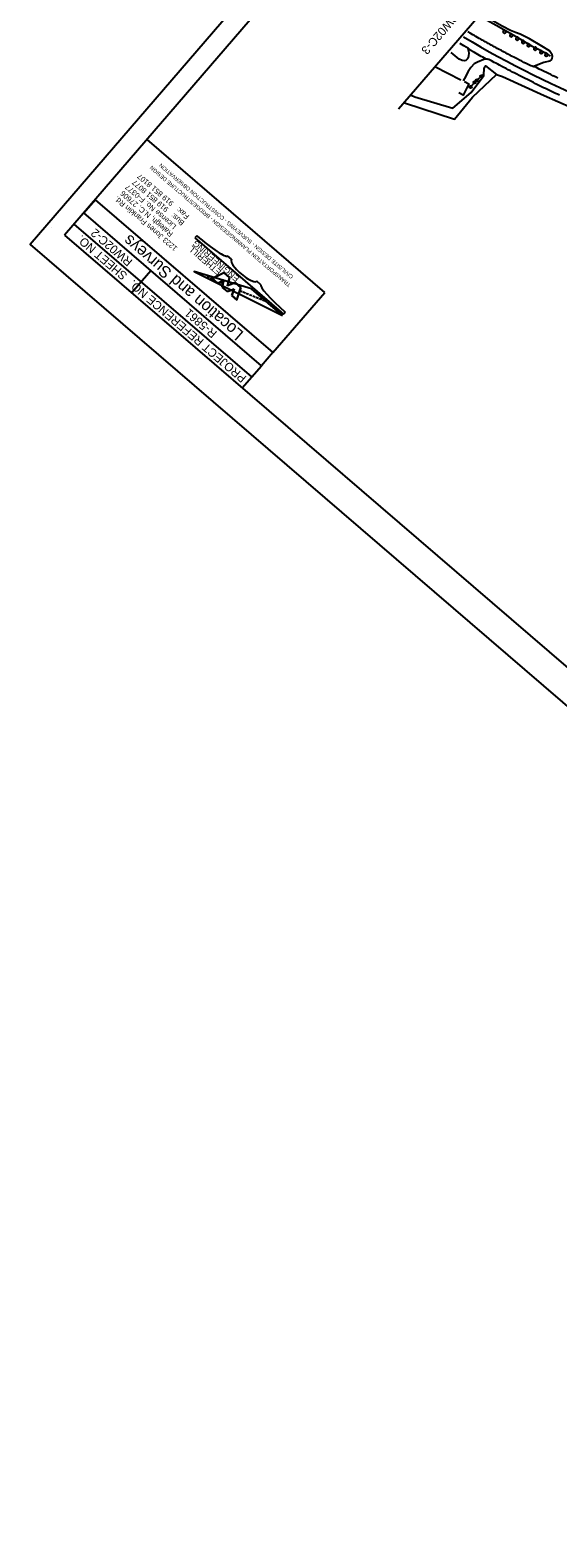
# Model space of a CAD drawing. Extents: x 478596 to 483012, y 490885 to 495165.
# Drawn here: x 478596 to 479587, y 490885 to 493722 of the extents above; entities that cross this region are included whole.
import ezdxf

# ---------------------------------------------------------------- set-up
doc = ezdxf.new("R2010")
doc.units = 0
for name, color, linetype in [('CTL Sheet Border CELL', 7, 'Continuous'), ('CTL Sheet Notes CELL', 7, 'Continuous'), ('Exist Horizontal Alignment', 7, 'Continuous'), ('Exist Other Culture Area Outline', 7, 'Continuous'), ('Exist Other Culture Fence Line', 7, 'Continuous'), ('Exist Other Culture Sign', 7, 'Continuous'), ('Exist Other Culture Sign Post CELL', 7, 'Continuous'), ('Exist Roads EOP', 7, 'Continuous'), ('Exist Roads Soil', 7, 'Continuous'), ('Exist Vegetation Hedge Row', 7, 'Continuous'), ('Exist Vegetation Shrub CELL', 7, 'Continuous'), ('Exist Vegetation Woods Line', 7, 'Continuous'), ('Matchline', 7, 'Continuous'), ('Matchline Text', 7, 'Continuous'), ('Sheet Plot Border Outside CELL', 7, 'Continuous')]:
    doc.layers.add(name, color=color, linetype=linetype)

msp = doc.modelspace()

# ---------------------------------------------------------------- linework, layer by layer
at = {"layer": 'CTL Sheet Border CELL'}
for p, q in [((479149.5, 493228.2), (478815.6, 493515.6)), ((478636, 493349.5), (478636, 493349.5)), ((478636, 493349.5), (478636, 493349.5)), ((479012.7, 493069.4), (478678.8, 493356.8)), ((478596, 493318.3), (478596, 493318.3)), ((478786.6, 493227.4), (478822.7, 493269.4)), ((479052, 493115), (479149.4, 493228.2)), ((478994.6, 493048.4), (479030.7, 493090.3))]:
    msp.add_line(p, q, dxfattribs=at)
for points in [[(478660.7, 493335.7), (481178.4, 491168.5), (482695.4, 492930.9), (480177.7, 495098.1)], [(479030.7, 493090.3), (478696.8, 493377.7), (478718.1, 493402.4), (479052, 493115)]]:
    msp.add_lwpolyline(points, close=True, dxfattribs=at)
at = {"layer": 'CTL Sheet Notes CELL'}
for p, q in [((478909, 493334.9), (478905.7, 493331.1)), ((478905.7, 493331.1), (479072.2, 493187.3)), ((478974.3, 493290.6), (478966.7, 493297.2)), ((478932.7, 493255.3), (478928.1, 493257.3)), ((478938.8, 493252.7), (478934.2, 493254.7)), ((478937.8, 493254.1), (478947.9, 493245.4)), ((478960.4, 493264.7), (478938.4, 493254)), ((478938.4, 493254), (478947.9, 493245.8)), ((478947.9, 493245.8), (478959.8, 493251.6)), ((478947.9, 493245.4), (478959.3, 493251)), ((478959.3, 493251), (478956.4, 493238.1)), ((478959.8, 493251.6), (478956.7, 493238.2)), ((478970.5, 493256), (478960.4, 493264.7)), ((478970.9, 493256.1), (478960.5, 493265.1)), ((478966.9, 493240.4), (478970.5, 493256)), ((478967.4, 493240.9), (478970.9, 493256.1)), ((479029.7, 493242.7), (479022.2, 493249.2)), ((478957.3, 493245), (478952.7, 493246.9)), ((478956.4, 493238.1), (478966.1, 493229.6)), ((478956.7, 493238.2), (478966.2, 493230)), ((478966.1, 493229.6), (478978.5, 493234.5)), ((478966.2, 493230), (478979.1, 493235)), ((478981.8, 493246.2), (478966.9, 493240.4)), ((478981.9, 493246.6), (478967.4, 493240.9)), ((478978.5, 493234.5), (478974.6, 493222.3)), ((478974.6, 493222.3), (478984.6, 493213.6)), ((478979.1, 493235), (478975, 493222.4)), ((478975, 493222.4), (478984.5, 493214.2)), ((478991.9, 493237.5), (478981.8, 493246.2)), ((478992.3, 493237.6), (478981.9, 493246.6)), ((478984.5, 493214.2), (478991.9, 493237.5)), ((478984.6, 493213.6), (478992.3, 493237.6)), ((478994.2, 493229.5), (478989.5, 493231.4)), ((479000.3, 493226.9), (478995.7, 493228.9)), ((479006.4, 493224.3), (479001.8, 493226.3)), ((479012.6, 493221.8), (479008, 493223.7)), ((479018.7, 493219.2), (479014.1, 493221.1)), ((479024.9, 493216.6), (479020.3, 493218.5)), ((479031, 493214), (479026.4, 493215.9)), ((479037.2, 493211.4), (479032.6, 493213.4)), ((479072.2, 493187.3), (479075.5, 493191.1))]:
    msp.add_line(p, q, dxfattribs=at)
msp.add_lwpolyline([(479070, 493184.8), (479012, 493234.9), (478904.3, 493267.3)], close=True, dxfattribs=at)
msp.add_lwpolyline([(478960.5, 493265.1), (478960.1, 493265), (478937.8, 493254.1)], dxfattribs=at)
for centre, major_axis, ratio, start_param, end_param in [((478915, 493341.8), (-51.7, 44.7), 0.134146, 1.570796, 3.141593), ((478998.2, 493269.9), (-24, 20.7), 0.289474, 0, 3.141593), ((479081.4, 493198), (51.7, -44.7), 0.134146, 3.141593, 4.712389)]:
    msp.add_ellipse(centre, major_axis=major_axis, ratio=ratio, start_param=start_param, end_param=end_param, dxfattribs=at)
at = {"layer": 'Exist Horizontal Alignment'}
msp.add_arc((480448.9, 495467.9), 2043, 239.4405, 247.8014, dxfattribs=at)
at = {"layer": 'Exist Other Culture Area Outline'}
for points in [[(479356.1, 493653), (479405.4, 493628.2)], [(479412.4, 493624.7), (479420.3, 493620.8), (479409.7, 493599.3), (479401.4, 493603.3)]]:
    msp.add_lwpolyline(points, dxfattribs=at)
at = {"layer": 'Exist Other Culture Fence Line'}
for points in [[(479517.7, 493704.2), (479494.8, 493716.8), (479471.4, 493730), (479449, 493742.6), (479438.1, 493748.4)], [(479517.7, 493704.2), (479538.3, 493692.1), (479551.1, 493685.6), (479562.8, 493679.5), (479573.1, 493672.4)]]:
    msp.add_lwpolyline(points, dxfattribs=at)
at = {"layer": 'Exist Other Culture Sign'}
for p, q in [((479433.4, 493625.7), (479422, 493613.4)), ((479446.4, 493637.7), (479434.5, 493626.2))]:
    msp.add_line(p, q, dxfattribs=at)
at = {"layer": 'Exist Other Culture Sign Post CELL'}
for centre, radius in [((479423.7, 493614.8), 2.18), ((479431.2, 493623.1), 2.18), ((479431.2, 493623.1), 0.24), ((479435.9, 493627), 2.18), ((479435.9, 493627), 0.24), ((479444, 493634.9), 2.18), ((479444, 493634.9), 0.24), ((479423.7, 493614.8), 0.24)]:
    msp.add_circle(centre, radius, dxfattribs=at)
at = {"layer": 'Exist Roads EOP'}
for points in [[(479587.7, 493631.1), (479583.1, 493633.4), (479578.4, 493635.7), (479574.3, 493637.8), (479570.3, 493639.7), (479566.2, 493641.7), (479561.9, 493643.8), (479557.1, 493646.1), (479552.6, 493648.4), (479547.3, 493651), (479544.6, 493652.3), (479543.3, 493652.8), (479540.5, 493653.2), (479539.4, 493653.6), (479536.8, 493654.7), (479533.2, 493656.3), (479527.8, 493658.9), (479523.9, 493660.8), (479519.8, 493662.9), (479515.6, 493665), (479511, 493667.4), (479506, 493669.9), (479500.7, 493672.7), (479497.9, 493674.2), (479495.1, 493675.7), (479492.3, 493677.2), (479489.6, 493678.7), (479486.8, 493680.1), (479484.1, 493681.6), (479481.4, 493683), (479476.2, 493685.8), (479473.6, 493687.2), (479470.9, 493688.7), (479468.1, 493690.2), (479465.3, 493691.7), (479462.5, 493693.3), (479459.7, 493694.9), (479456.8, 493696.4), (479454, 493698), (479451.2, 493699.6), (479448.3, 493701.2), (479445.5, 493702.8), (479442.6, 493704.5), (479439.6, 493706.1), (479436.7, 493707.8), (479433.7, 493709.5), (479430.7, 493711.3), (479427.8, 493713), (479422.7, 493716), (479418.7, 493718.4)], [(479590.8, 493599), (479586.9, 493600.8), (479583.1, 493602.6), (479579.3, 493604.4), (479575.5, 493606.1), (479571.7, 493607.9), (479568.1, 493609.7), (479564.4, 493611.5), (479560.8, 493613.3), (479557.1, 493615.1), (479553.3, 493617), (479549.4, 493618.9), (479545.5, 493620.8), (479541.6, 493622.8), (479537.8, 493624.7), (479534, 493626.6), (479530.3, 493628.5), (479526.4, 493630.5), (479522.6, 493632.4), (479518.7, 493634.4), (479514.7, 493636.4), (479510.7, 493638.5), (479506.7, 493640.5), (479502.6, 493642.6), (479498.5, 493644.7), (479494.4, 493646.9), (479490.3, 493649.1), (479486.1, 493651.2), (479482.1, 493653.4), (479478.2, 493655.4), (479474.6, 493657.3), (479471.2, 493659.1), (479468.2, 493660.7), (479463, 493663.5), (479457.6, 493666), (479455.9, 493666.6), (479455.2, 493666.8), (479453.5, 493667), (479452.9, 493667.2), (479449.5, 493669), (479446.7, 493670.5), (479443.5, 493672.2), (479440.3, 493674), (479437.1, 493675.8), (479433.9, 493677.6), (479431, 493679.2), (479428.6, 493680.6), (479423.9, 493683.5), (479422.9, 493684.3), (479421.4, 493685.6), (479419.4, 493687.2), (479415.5, 493689.6), (479410.9, 493692.3), (479408, 493694), (479404.7, 493695.9), (479403.5, 493696.7)]]:
    msp.add_lwpolyline(points, dxfattribs=at)
at = {"layer": 'Exist Roads Soil'}
for points in [[(479516.6, 493714.2), (479507.7, 493716.9), (479498.6, 493720.6), (479482.9, 493728.7), (479465.1, 493738.8), (479451.8, 493745.9), (479442, 493750.3)], [(479575.8, 493677.2), (479571.9, 493682.7), (479557.7, 493691.2), (479534.3, 493705.4), (479516.6, 493714.2)], [(479418.5, 493686.8), (479419.4, 493682.6), (479420.3, 493677.5), (479419.8, 493673.7), (479419, 493669.7), (479417.8, 493667.4), (479414.5, 493664.7), (479411.7, 493664.1), (479407.6, 493664.6), (479402.2, 493667.2), (479386.8, 493679.7)], [(479540.3, 493653.1), (479546.6, 493655.6), (479561.2, 493661.1), (479573.4, 493664.1), (479575.8, 493665.5), (479577.1, 493668.4), (479577.7, 493671.9), (479576.9, 493675.2), (479575.8, 493677.2)], [(479453.1, 493667), (479448.5, 493666.3), (479436.7, 493661.2), (479430.4, 493657.9), (479424, 493651), (479419.2, 493643.6), (479412.3, 493630.3), (479409.9, 493626)]]:
    msp.add_lwpolyline(points, dxfattribs=at)
at = {"layer": 'Exist Vegetation Hedge Row'}
msp.add_lwpolyline([(479312, 493599.5), (479318.9, 493596), (479390, 493574.7), (479424.9, 493604.3), (479448.3, 493636.4), (479448.9, 493650.5), (479451.9, 493654.2), (479472.5, 493638.3)], dxfattribs=at)
at = {"layer": 'Exist Vegetation Shrub CELL'}
for p, q in [((479487.2, 493718.4), (479487.2, 493718.4)), ((479499.9, 493711.7), (479499.9, 493711.7)), ((479511.3, 493705.4), (479511.3, 493705.4)), ((479522.4, 493699), (479522.4, 493699)), ((479532.5, 493693), (479532.5, 493693)), ((479545.1, 493686.6), (479545.1, 493686.6)), ((479556.4, 493680), (479556.4, 493680)), ((479565.9, 493675.1), (479565.9, 493675.1))]:
    msp.add_line(p, q, dxfattribs=at)
for centre, radius, start, end in [((479485.4, 493717.7), 0.955, 95.1099, 327.9534), ((479485.7, 493719.5), 0.968, 35.8908, 245.4216), ((479487.1, 493716.7), 0.984, 151.2797, 21.387), ((479487.4, 493720.5), 0.99, 334.8391, 200.4717), ((479488.8, 493717.5), 0.937, 204.9913, 73.4601), ((479488.9, 493719.3), 0.929, 284.4567, 126.0861), ((479498.1, 493711), 0.955, 95.1099, 327.9534), ((479498.4, 493712.8), 0.968, 35.8908, 245.4216), ((479499.8, 493710), 0.984, 151.2797, 21.387), ((479500.1, 493713.7), 0.99, 334.8391, 200.4717), ((479501.6, 493710.8), 0.937, 204.9913, 73.4601), ((479501.6, 493712.6), 0.929, 284.4567, 126.0861), ((479509.5, 493704.7), 0.955, 95.1099, 327.9534), ((479509.8, 493706.5), 0.968, 35.8908, 245.4216), ((479511.1, 493703.7), 0.984, 151.2797, 21.387), ((479511.5, 493707.4), 0.99, 334.8391, 200.4717), ((479512.9, 493704.4), 0.937, 204.9913, 73.4601), ((479512.9, 493706.2), 0.929, 284.4567, 126.0861), ((479522.6, 493701), 0.99, 334.8391, 200.4717), ((479520.6, 493698.3), 0.955, 95.1099, 327.9534), ((479520.9, 493700.1), 0.968, 35.8908, 245.4216), ((479522.2, 493697.3), 0.984, 151.2797, 21.387), ((479524, 493698), 0.937, 204.9913, 73.4601), ((479524, 493699.8), 0.929, 284.4567, 126.0861), ((479530.7, 493692.3), 0.955, 95.1099, 327.9534), ((479531, 493694.1), 0.968, 35.8908, 245.4216), ((479532.4, 493691.3), 0.984, 151.2797, 21.387), ((479532.7, 493695), 0.99, 334.8391, 200.4717), ((479534.2, 493692.1), 0.937, 204.9913, 73.4601), ((479534.2, 493693.9), 0.929, 284.4567, 126.0861), ((479543.3, 493685.9), 0.955, 95.1099, 327.9534), ((479543.6, 493687.7), 0.968, 35.8908, 245.4216), ((479545, 493684.9), 0.984, 151.2797, 21.387), ((479545.4, 493688.6), 0.99, 334.8391, 200.4717), ((479546.8, 493685.7), 0.937, 204.9913, 73.4601), ((479546.8, 493687.5), 0.929, 284.4567, 126.0861), ((479554.6, 493679.3), 0.955, 95.1099, 327.9534), ((479554.9, 493681.1), 0.968, 35.8908, 245.4216), ((479556.3, 493678.3), 0.984, 151.2797, 21.387), ((479556.6, 493682), 0.99, 334.8391, 200.4717), ((479558, 493679), 0.937, 204.9913, 73.4601), ((479558.1, 493680.8), 0.929, 284.4567, 126.0861), ((479564.1, 493674.4), 0.955, 95.1099, 327.9534), ((479564.4, 493676.2), 0.968, 35.8908, 245.4216), ((479565.8, 493673.4), 0.984, 151.2797, 21.387), ((479566.1, 493677.1), 0.99, 334.8391, 200.4717), ((479567.5, 493674.1), 0.937, 204.9913, 73.4601), ((479567.6, 493675.9), 0.929, 284.4567, 126.0861)]:
    msp.add_arc(centre, radius, start, end, dxfattribs=at)
at = {"layer": 'Exist Vegetation Woods Line'}
for points in [[(479299.3, 493584.5), (479393.3, 493554), (479427.4, 493595.7), (479472.5, 493638.3), (479483.5, 493634.2)], [(479483.5, 493634.2), (479562, 493598.6), (479741.9, 493519.7), (479786.2, 493503), (479770.2, 493467.4), (479736.5, 493479.4), (479725.7, 493453.7), (479755.9, 493427.2), (479747.5, 493411.6), (479741.5, 493386.2), (479749.8, 493380.9), (479748.2, 493352.9), (479746.7, 493346.3)]]:
    msp.add_lwpolyline(points, dxfattribs=at)
at = {"layer": 'Matchline'}
msp.add_line((479288.4, 493573.4), (479614.6, 493952.4), dxfattribs=at)
at = {"layer": 'Sheet Plot Border Outside CELL'}
msp.add_lwpolyline([(483011.9, 492731.6), (480185.3, 495164.6), (478596, 493318.3), (481422.6, 490885.3)], close=True, dxfattribs=at)

# ---------------------------------------------------------------- texts
at = {"layer": 'CTL Sheet Border CELL'}
for s, height, p in [('SHEET NO.', 16, (478779.8, 493262.1)), ('RW02C-2', 16, (478789.8, 493288.1)), ('Location and Surveys', 22.147, (478998.6, 493152.6)), ('PROJECT REFERENCE NO.', 16, (479003.7, 493069.1)), ('R-5861', 16, (478948.2, 493153))]:
    msp.add_text(s, height=height, rotation=139.2795, dxfattribs=at).set_placement(p)
at = {"layer": 'CTL Sheet Notes CELL'}
for s, height, rotation, p in [('Fax:   919 851 8107', 10, 139.4981, (478895.9, 493372.4)), ('TRANSPORTATION PLANNING/DESIGN - BRIDGE/STRUCTURE DESIGN', 7.333, 139.4981, (479086.4, 493243.3)), ('CIVIL/SITE DESIGN - SURVEYING - CONSTRUCTION OBSERVATION', 7.333, 139.4981, (479091.1, 493258.6)), ('License No. F-0377', 10, 139.4981, (478871.5, 493353.7)), ('Bus:   919 851 8077', 10, 139.4981, (478886.7, 493360.5)), ('1223 Jones Franklin Rd. ', 10, 139.4981, (478873.5, 493312.5)), ('Raleigh, N.C. 27606', 10, 139.4981, (478865.2, 493339.4)), ('ETHERILL', 11.67, 139.1716, (478956.2, 493268.3)), ('ENGINEERING', 11.667, 139.1716, (478990.2, 493255.9))]:
    msp.add_text(s, height=height, rotation=rotation, dxfattribs=at).set_placement(p)
at = {"layer": 'Matchline Text'}
msp.add_text('MATCHLINE SHEET RW02C-3', height=16, rotation=229.5222, dxfattribs=at).set_placement((479525, 493913.3))

doc.saveas('drawing.dxf')
